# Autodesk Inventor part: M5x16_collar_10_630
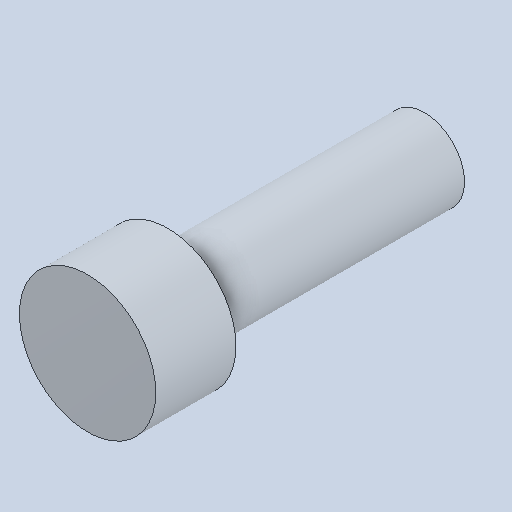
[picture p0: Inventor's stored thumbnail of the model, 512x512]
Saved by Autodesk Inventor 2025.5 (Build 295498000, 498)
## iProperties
Created: 2026-10
Part Number: M5x16_collar_10_630
Material: Genérico
Document SubType Name: Modeling
Designer: Luis M
Density: 1 g/cm^3
Appearance: Valor por defecto
Author: Luis M
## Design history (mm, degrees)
feature "Base1"
node "Sólido1"
